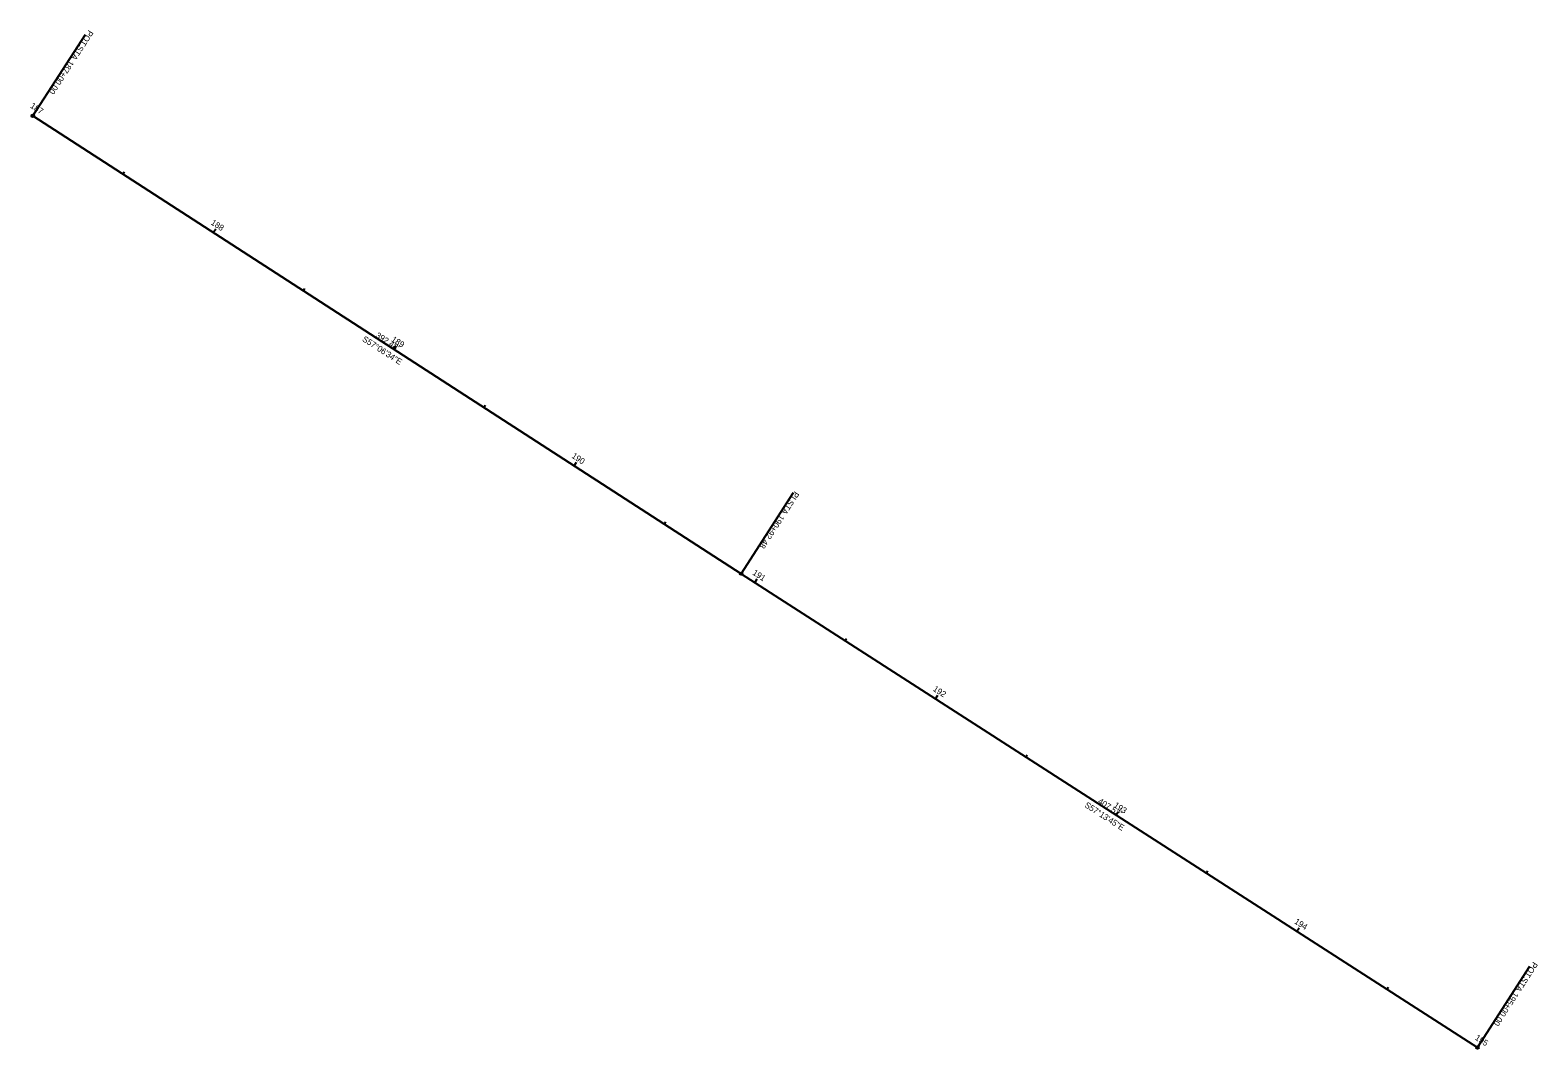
# Model space of a CAD drawing. Extents: x 196968 to 197670, y 275810 to 276284.
import ezdxf

# ---------------------------------------------------------------- set-up
doc = ezdxf.new("R2010")
doc.units = 0
for name, color, linetype in [('GE_P_Alignment', 7, 'Continuous'), ('GE_P_Alignment_100_Bearings', 7, 'Continuous'), ('GE_P_Alignment_100_Cardinal_Points', 7, 'Continuous'), ('GE_P_Alignment_100_Curve_Data', 7, 'Continuous'), ('SC_Scratch1', 7, 'Continuous'), ('SC_Scratch2', 7, 'Continuous')]:
    doc.layers.add(name, color=color, linetype=linetype)

msp = doc.modelspace()

# ---------------------------------------------------------------- linework, layer by layer
at = {"layer": 'GE_P_Alignment'}
for p, q in [((196969.36, 276244.04), (197298.93, 276030.9)), ((197298.93, 276030.9), (197641.59, 275810.32))]:
    msp.add_line(p, q, dxfattribs=at)
at = {"layer": 'GE_P_Alignment_100_Bearings'}
for p, q in [((196969.36, 276244.04), (196993.8, 276281.82)), ((197298.93, 276030.9), (197323.29, 276068.74)), ((197641.59, 275810.32), (197665.95, 275848.16))]:
    msp.add_line(p, q, dxfattribs=at)
for centre in [(196969.36, 276244.04), (197298.93, 276030.9), (197641.59, 275810.32)]:
    msp.add_circle(centre, 0.6, dxfattribs=at)
at = {"layer": 'GE_P_Alignment_100_Curve_Data'}
for p, q in [((196969.36, 276244.04), (196970.45, 276245.72)), ((197011.35, 276216.88), (197012, 276217.89)), ((197053.33, 276189.73), (197054.42, 276191.41)), ((197095.32, 276162.58), (197095.97, 276163.59)), ((197137.31, 276135.43), (197138.39, 276137.11)), ((197179.29, 276108.28), (197179.94, 276109.28)), ((197221.28, 276081.12), (197222.36, 276082.8)), ((197263.26, 276053.97), (197263.91, 276054.98)), ((197305.26, 276026.83), (197306.34, 276028.52)), ((197347.3, 275999.77), (197347.95, 276000.78)), ((197389.34, 275972.71), (197390.42, 275974.39)), ((197431.38, 275945.64), (197432.03, 275946.65)), ((197473.42, 275918.58), (197474.51, 275920.26)), ((197515.47, 275891.51), (197516.12, 275892.52)), ((197557.51, 275864.45), (197558.59, 275866.13)), ((197599.55, 275837.39), (197600.2, 275838.4)), ((197641.59, 275810.32), (197642.67, 275812))]:
    msp.add_line(p, q, dxfattribs=at)
at = {"layer": 'SC_Scratch1'}
for q in [(196969.36, 276244.04), (197641.59, 275810.32)]:
    msp.add_line((197298.93, 276030.9), q, dxfattribs=at)

# ---------------------------------------------------------------- texts
at = {"layer": 'GE_P_Alignment_100_Bearings'}
for s, rotation, p in [('POT', 237.10931, (196995.36, 276284.15)), (' STA. ', 237.10931, (196991.45, 276278.1)), ('187+00.00', 237.10931, (196986.31, 276270.17)), (' STA. ', 237.22913, (197321.97, 276066.61)), ('PI', 237.22913, (197323.8, 276069.46)), ('190+92.48', 237.22913, (197316.85, 276058.66)), ('POT', 237.22913, (197667.5, 275850.49)), (' STA. ', 237.22913, (197663.6, 275844.44)), ('195+00.00', 237.22913, (197658.49, 275836.49))]:
    msp.add_text(s, height=2.8, rotation=rotation, dxfattribs=at).set_placement(p)
at = {"layer": 'GE_P_Alignment_100_Cardinal_Points'}
for s, rotation, p in [("392.48'", 327.10931, (197128.56, 276141.13)), ("407.52'", 327.22913, (197464.67, 275924.26))]:
    msp.add_text(s, height=2.8, rotation=rotation, dxfattribs=at).set_placement(p)
at = {"layer": 'GE_P_Alignment_100_Curve_Data'}
for s, rotation, p in [('187', 327.10931, (196967.85, 276247.99)), ('188', 327.10931, (197051.89, 276193.64)), ('189', 327.10931, (197135.88, 276139.33)), ('190', 327.10931, (197219.82, 276085.04)), ('191', 327.22913, (197303.96, 276030.64)), ('192', 327.22913, (197387.94, 275976.58)), ('193', 327.22913, (197472.03, 275922.45)), ('194', 327.22913, (197556.11, 275868.32)), ('195', 327.22913, (197640.17, 275814.21))]:
    msp.add_text(s, height=2.8, rotation=rotation, dxfattribs=at).set_placement(p)
at = {"layer": 'SC_Scratch2'}
for s, rotation, p in [('S57°06\'34"E', 327.10931, (197122.36, 276139.38)), ('S57°13\'45"E', 327.22913, (197458.47, 275922.5))]:
    msp.add_text(s, height=2.8, rotation=rotation, dxfattribs=at).set_placement(p)

doc.saveas('drawing.dxf')
